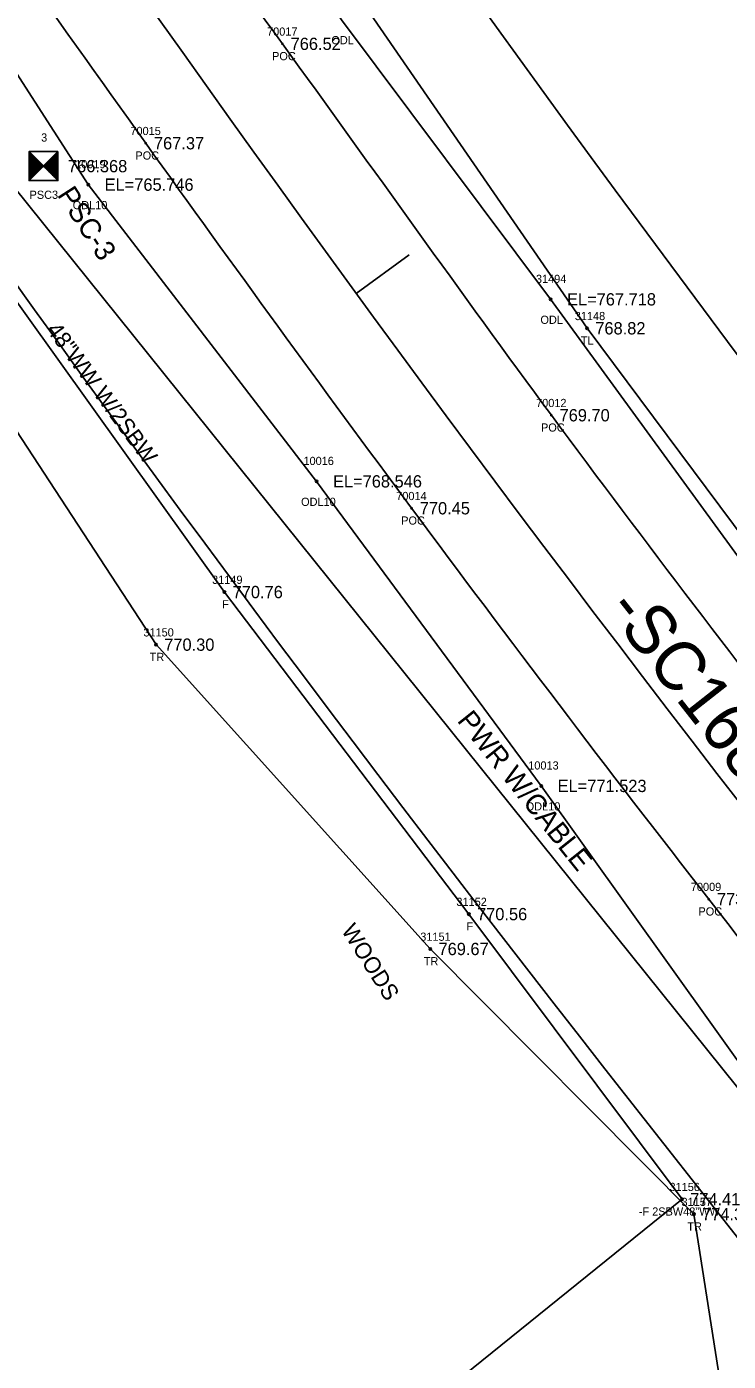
# Model space of a CAD drawing. Extents: x 1375131 to 1378678, y 999028 to 1004053.
# Drawn here: x 1378040.5 to 1378126.3, y 1000372 to 1000535.2 of the extents above; entities that cross this region are included whole.
import ezdxf

# ---------------------------------------------------------------- set-up
doc = ezdxf.new("R2010")
doc.units = 0
for name, color, linetype in [('RD_EX_Fence_Other', 7, 'Continuous'), ('RD_EX_Fence_Other_txCode', 7, 'Continuous'), ('RD_EX_H2O', 7, 'Continuous'), ('RD_EX_H2O_txCode', 7, 'Continuous'), ('RD_EX_Road', 7, 'Continuous'), ('RD_EX_Road_txCode', 7, 'Continuous'), ('RD_EX_RW', 7, 'Continuous'), ('RD_EX_SU_Elec', 7, 'Continuous'), ('RD_EX_TX_Fence_Other_ELEV', 7, 'Continuous'), ('RD_EX_TX_H2O_ELEV', 7, 'Continuous'), ('RD_EX_TX_Road_ELEV', 7, 'Continuous'), ('RD_EX_TX_VEG_ELEV', 7, 'Continuous'), ('RD_EX_VEG', 7, 'Continuous'), ('RD_EX_VEG_txCode', 7, 'Continuous'), ('RD_HC_Cl', 7, 'Continuous'), ('RD_HC_Data', 7, 'Continuous'), ('RD_HC_Data_Tic', 7, 'Continuous'), ('RD_HC_Survey', 7, 'Continuous'), ('RD_HC_Survey_ELEV', 7, 'Continuous'), ('RD_HC_txCode', 7, 'Continuous'), ('RD_SMD_Locator', 7, 'Continuous'), ('RD_TX_Misc1', 7, 'Continuous'), ('RD_TX_Misc2', 7, 'Continuous'), ('RD_TX_Utilities', 7, 'Continuous')]:
    doc.layers.add(name, color=color, linetype=linetype)

msp = doc.modelspace()

# ---------------------------------------------------------------- linework, layer by layer
at = {"layer": 'RD_EX_Fence_Other'}
msp.add_line((1378120.64, 1000391.86), (1378063.92, 1000346.11), dxfattribs=at)
msp.add_lwpolyline([(1377931.18, 1000664.74), (1377962.69, 1000614.46), (1378000.62, 1000557.28), (1378027.91, 1000517.45), (1378064.7, 1000466.08), (1378094.58, 1000426.71), (1378120.64, 1000391.86)], dxfattribs=at)
at = {"layer": 'RD_EX_H2O'}
for points in [[(1378150.92, 1000378.55), (1378129.93, 1000405.36), (1378103.43, 1000442.38), (1378075.97, 1000479.61), (1378048.05, 1000515.88), (1378024, 1000553.21), (1377996.39, 1000591.76), (1377970.53, 1000631.66), (1377963.48, 1000646.08)], [(1378187.96, 1000391.62), (1378166.95, 1000418.07), (1378136.83, 1000457.58), (1378104.58, 1000501.86), (1378079.02, 1000536.04), (1378053.9, 1000573.86), (1378029.31, 1000608.17), (1378022.93, 1000618.73)]]:
    msp.add_lwpolyline(points, dxfattribs=at)
at = {"layer": 'RD_EX_Road'}
for points in [[(1378177.15, 1000392.85), (1378139.73, 1000441.52), (1378104.67, 1000487.69), (1378071.79, 1000533.09), (1378038.45, 1000579.8), (1378007.55, 1000627.96), (1377974.27, 1000678.86), (1377944.47, 1000727.12), (1377913.03, 1000778.58), (1377899.67, 1000800.29)], [(1378161.36, 1000381.16), (1378123.91, 1000428.54), (1378087.58, 1000476.32), (1378055.08, 1000520.94), (1378021.67, 1000568.71), (1377989.95, 1000617.08), (1377957.33, 1000668.38), (1377927.53, 1000716.55), (1377895.41, 1000768.82), (1377883.75, 1000788.5)]]:
    msp.add_spline(points, degree=3, dxfattribs=at)
at = {"layer": 'RD_EX_RW'}
msp.add_line((1378111.22, 1000407.8), (1378147.34, 1000361.8), dxfattribs=at)
for radius in [2667, 2733]:
    msp.add_arc((1380260.77, 1002095.62), radius, 211.36799, 218.13892, dxfattribs=at)
at = {"layer": 'RD_EX_SU_Elec'}
msp.add_lwpolyline([(1377798.03, 1000893.79), (1378025.9, 1000531.77), (1378278.5, 1000217.55)], dxfattribs=at)
at = {"layer": 'RD_EX_VEG'}
for points in [[(1377698.52, 1000917.3), (1377753.14, 1000944.68), (1377782.86, 1000890.37), (1377819.02, 1000831), (1377844.41, 1000789.91), (1377879.22, 1000734.35), (1377912.22, 1000680.73), (1377954.28, 1000611.32), (1377992.95, 1000554.02), (1378022.09, 1000512.01), (1378056.34, 1000459.65), (1378089.87, 1000422.45), (1378122.09, 1000390.03), (1378125.27, 1000369.76), (1378093.99, 1000348.6)], [(1377975.86, 1000867.47), (1377940.96, 1000846.12), (1377905.66, 1000824.77), (1377936.14, 1000772.34), (1377973.26, 1000709.66), (1378011.8, 1000643.94), (1378051.79, 1000581.32), (1378077.27, 1000544.45), (1378109.04, 1000498.32), (1378149.58, 1000443.93), (1378185.36, 1000398.58)]]:
    msp.add_lwpolyline(points, dxfattribs=at)
at = {"layer": 'RD_HC_Cl'}
msp.add_arc((1380260.77, 1002095.62), 2700, 211.36799, 218.13892, dxfattribs=at)
at = {"layer": 'RD_HC_Data_Tic'}
msp.add_line((1378080.81, 1000502.58), (1378087.27, 1000507.3), dxfattribs=at)
at = {"layer": 'RD_HC_Survey'}
for p, q in [((1378040.81, 1000519.91), (1378044.34, 1000516.37)), ((1378044.34, 1000519.91), (1378040.81, 1000516.37)), ((1378040.83, 1000519.88), (1378040.83, 1000516.4)), ((1378040.86, 1000519.86), (1378040.86, 1000516.42)), ((1378040.88, 1000519.83), (1378040.88, 1000516.45)), ((1378040.91, 1000519.81), (1378040.91, 1000516.47)), ((1378040.93, 1000519.78), (1378040.93, 1000516.5)), ((1378040.96, 1000519.76), (1378040.96, 1000516.52)), ((1378040.98, 1000519.73), (1378040.98, 1000516.55)), ((1378041.01, 1000519.71), (1378041.01, 1000516.57)), ((1378041.03, 1000519.68), (1378041.03, 1000516.6)), ((1378041.06, 1000519.66), (1378041.06, 1000516.62)), ((1378041.08, 1000519.63), (1378041.08, 1000516.65)), ((1378041.11, 1000519.61), (1378041.11, 1000516.67)), ((1378041.13, 1000519.58), (1378041.13, 1000516.7)), ((1378041.16, 1000519.56), (1378041.16, 1000516.72)), ((1378041.18, 1000519.53), (1378041.18, 1000516.75)), ((1378041.21, 1000519.51), (1378041.21, 1000516.77)), ((1378041.23, 1000519.48), (1378041.23, 1000516.8)), ((1378041.26, 1000519.46), (1378041.26, 1000516.82)), ((1378041.28, 1000519.43), (1378041.28, 1000516.85)), ((1378041.31, 1000519.41), (1378041.31, 1000516.87)), ((1378041.33, 1000519.38), (1378041.33, 1000516.9)), ((1378041.36, 1000519.36), (1378041.36, 1000516.92)), ((1378041.38, 1000519.33), (1378041.38, 1000516.95)), ((1378041.41, 1000519.31), (1378041.41, 1000516.97)), ((1378041.43, 1000519.28), (1378041.43, 1000517)), ((1378041.46, 1000519.26), (1378041.46, 1000517.02)), ((1378041.48, 1000519.23), (1378041.48, 1000517.05)), ((1378041.51, 1000519.21), (1378041.51, 1000517.07)), ((1378043.64, 1000519.21), (1378043.64, 1000517.07)), ((1378043.67, 1000519.23), (1378043.67, 1000517.05)), ((1378043.69, 1000519.26), (1378043.69, 1000517.02)), ((1378043.72, 1000519.28), (1378043.72, 1000517)), ((1378043.74, 1000519.31), (1378043.74, 1000516.97)), ((1378043.77, 1000519.33), (1378043.77, 1000516.95)), ((1378043.79, 1000519.36), (1378043.79, 1000516.92)), ((1378043.82, 1000519.38), (1378043.82, 1000516.9)), ((1378043.84, 1000519.41), (1378043.84, 1000516.87)), ((1378043.87, 1000519.43), (1378043.87, 1000516.85)), ((1378043.89, 1000519.46), (1378043.89, 1000516.82)), ((1378043.92, 1000519.48), (1378043.92, 1000516.8)), ((1378043.94, 1000519.51), (1378043.94, 1000516.77)), ((1378043.97, 1000519.53), (1378043.97, 1000516.75)), ((1378043.99, 1000519.56), (1378043.99, 1000516.72)), ((1378044.02, 1000519.58), (1378044.02, 1000516.7)), ((1378044.04, 1000519.61), (1378044.04, 1000516.67)), ((1378044.07, 1000519.63), (1378044.07, 1000516.65)), ((1378044.09, 1000519.66), (1378044.09, 1000516.62)), ((1378044.12, 1000519.68), (1378044.12, 1000516.6)), ((1378044.14, 1000519.71), (1378044.14, 1000516.57)), ((1378044.17, 1000519.73), (1378044.17, 1000516.55)), ((1378044.19, 1000519.76), (1378044.19, 1000516.52)), ((1378044.22, 1000519.78), (1378044.22, 1000516.5)), ((1378044.24, 1000519.81), (1378044.24, 1000516.47)), ((1378044.27, 1000519.83), (1378044.27, 1000516.45)), ((1378044.29, 1000519.86), (1378044.29, 1000516.42)), ((1378044.32, 1000519.88), (1378044.32, 1000516.4)), ((1378041.53, 1000519.18), (1378041.53, 1000517.1)), ((1378041.56, 1000519.16), (1378041.56, 1000517.12)), ((1378041.58, 1000519.13), (1378041.58, 1000517.15)), ((1378041.61, 1000519.11), (1378041.61, 1000517.17)), ((1378041.63, 1000519.08), (1378041.63, 1000517.2)), ((1378041.66, 1000519.06), (1378041.66, 1000517.22)), ((1378041.68, 1000519.03), (1378041.68, 1000517.25)), ((1378041.71, 1000519.01), (1378041.71, 1000517.27)), ((1378041.73, 1000518.98), (1378041.73, 1000517.3)), ((1378041.76, 1000518.96), (1378041.76, 1000517.32)), ((1378041.78, 1000518.93), (1378041.78, 1000517.35)), ((1378041.81, 1000518.91), (1378041.81, 1000517.37)), ((1378041.83, 1000518.88), (1378041.83, 1000517.4)), ((1378041.86, 1000518.86), (1378041.86, 1000517.42)), ((1378041.88, 1000518.83), (1378041.88, 1000517.45)), ((1378041.91, 1000518.81), (1378041.91, 1000517.47)), ((1378041.93, 1000518.78), (1378041.93, 1000517.5)), ((1378041.96, 1000518.76), (1378041.96, 1000517.52)), ((1378041.98, 1000518.73), (1378041.98, 1000517.55)), ((1378042.01, 1000518.71), (1378042.01, 1000517.57)), ((1378042.03, 1000518.68), (1378042.03, 1000517.6)), ((1378042.06, 1000518.66), (1378042.06, 1000517.62)), ((1378042.08, 1000518.63), (1378042.08, 1000517.65)), ((1378042.11, 1000518.61), (1378042.11, 1000517.67)), ((1378042.13, 1000518.58), (1378042.13, 1000517.7)), ((1378042.16, 1000518.56), (1378042.16, 1000517.72)), ((1378042.18, 1000518.53), (1378042.18, 1000517.75)), ((1378042.21, 1000518.51), (1378042.21, 1000517.77)), ((1378042.23, 1000518.48), (1378042.23, 1000517.8)), ((1378042.26, 1000518.46), (1378042.26, 1000517.82)), ((1378042.28, 1000518.43), (1378042.28, 1000517.85)), ((1378042.31, 1000518.41), (1378042.31, 1000517.87)), ((1378042.33, 1000518.38), (1378042.33, 1000517.9)), ((1378042.36, 1000518.36), (1378042.36, 1000517.92)), ((1378042.38, 1000518.33), (1378042.38, 1000517.95)), ((1378042.41, 1000518.31), (1378042.41, 1000517.97)), ((1378042.43, 1000518.28), (1378042.43, 1000518)), ((1378042.46, 1000518.26), (1378042.46, 1000518.02)), ((1378042.48, 1000518.23), (1378042.48, 1000518.05)), ((1378042.51, 1000518.21), (1378042.51, 1000518.07)), ((1378042.53, 1000518.18), (1378042.53, 1000518.1)), ((1378042.56, 1000518.16), (1378042.56, 1000518.12)), ((1378042.59, 1000518.16), (1378042.59, 1000518.12)), ((1378042.62, 1000518.18), (1378042.62, 1000518.1)), ((1378042.64, 1000518.21), (1378042.64, 1000518.07)), ((1378042.67, 1000518.23), (1378042.67, 1000518.05)), ((1378042.69, 1000518.26), (1378042.69, 1000518.02)), ((1378042.72, 1000518.28), (1378042.72, 1000518)), ((1378042.74, 1000518.31), (1378042.74, 1000517.97)), ((1378042.77, 1000518.33), (1378042.77, 1000517.95)), ((1378042.79, 1000518.36), (1378042.79, 1000517.92)), ((1378042.82, 1000518.38), (1378042.82, 1000517.9)), ((1378042.84, 1000518.41), (1378042.84, 1000517.87)), ((1378042.87, 1000518.43), (1378042.87, 1000517.85)), ((1378042.89, 1000518.46), (1378042.89, 1000517.82)), ((1378042.92, 1000518.48), (1378042.92, 1000517.8)), ((1378042.94, 1000518.51), (1378042.94, 1000517.77)), ((1378042.97, 1000518.53), (1378042.97, 1000517.75)), ((1378042.99, 1000518.56), (1378042.99, 1000517.72)), ((1378043.02, 1000518.58), (1378043.02, 1000517.7)), ((1378043.04, 1000518.61), (1378043.04, 1000517.67)), ((1378043.07, 1000518.63), (1378043.07, 1000517.65)), ((1378043.09, 1000518.66), (1378043.09, 1000517.62)), ((1378043.12, 1000518.68), (1378043.12, 1000517.6)), ((1378043.14, 1000518.71), (1378043.14, 1000517.57)), ((1378043.17, 1000518.73), (1378043.17, 1000517.55)), ((1378043.19, 1000518.76), (1378043.19, 1000517.52)), ((1378043.22, 1000518.78), (1378043.22, 1000517.5)), ((1378043.24, 1000518.81), (1378043.24, 1000517.47)), ((1378043.27, 1000518.83), (1378043.27, 1000517.45)), ((1378043.29, 1000518.86), (1378043.29, 1000517.42)), ((1378043.32, 1000518.88), (1378043.32, 1000517.4)), ((1378043.34, 1000518.91), (1378043.34, 1000517.37)), ((1378043.37, 1000518.93), (1378043.37, 1000517.35)), ((1378043.39, 1000518.96), (1378043.39, 1000517.32)), ((1378043.42, 1000518.98), (1378043.42, 1000517.3)), ((1378043.44, 1000519.01), (1378043.44, 1000517.27)), ((1378043.47, 1000519.03), (1378043.47, 1000517.25)), ((1378043.49, 1000519.06), (1378043.49, 1000517.22)), ((1378043.52, 1000519.08), (1378043.52, 1000517.2)), ((1378043.54, 1000519.11), (1378043.54, 1000517.17)), ((1378043.57, 1000519.13), (1378043.57, 1000517.15)), ((1378043.59, 1000519.16), (1378043.59, 1000517.12)), ((1378043.62, 1000519.18), (1378043.62, 1000517.1))]:
    msp.add_line(p, q, dxfattribs=at)
msp.add_lwpolyline([(1378044.34, 1000519.91), (1378040.81, 1000519.91), (1378040.81, 1000516.37), (1378044.34, 1000516.37)], close=True, dxfattribs=at)
at = {"layer": 'RD_SMD_Locator'}
for centre, radius in [((1378071.79, 1000533.09), 0.075), ((1378055.08, 1000520.94), 0.075), ((1378042.57, 1000518.14), 0.075), ((1378048.05, 1000515.88), 0.15), ((1378104.58, 1000501.86), 0.15), ((1378109.04, 1000498.32), 0.15), ((1378104.67, 1000487.69), 0.075), ((1378075.97, 1000479.61), 0.15), ((1378087.58, 1000476.32), 0.075), ((1378064.7, 1000466.08), 0.15), ((1378056.34, 1000459.65), 0.15), ((1378103.43, 1000442.38), 0.15), ((1378123.91, 1000428.54), 0.075), ((1378094.58, 1000426.71), 0.15), ((1378089.87, 1000422.45), 0.15), ((1378120.64, 1000391.86), 0.15), ((1378122.09, 1000390.03), 0.15)]:
    msp.add_circle(centre, radius, dxfattribs=at)

# ---------------------------------------------------------------- texts
at = {"layer": 'RD_EX_Fence_Other_txCode'}
for s, p in [('31149', (1378063.19, 1000467.08)), ('F', (1378064.42, 1000464.08)), ('31152', (1378093.06, 1000427.71)), ('F', (1378094.29, 1000424.71)), ('31156', (1378119.11, 1000392.86)), ('-F 2SBW48"WW', (1378115.36, 1000389.86))]:
    msp.add_text(s, height=1, dxfattribs=at).set_placement(p)
at = {"layer": 'RD_EX_H2O_txCode'}
for s, p in [('ODL', (1378077.77, 1000533.04)), ('10019', (1378046.45, 1000517.88)), ('ODL10', (1378046.15, 1000512.88)), ('31494', (1378102.78, 1000503.86)), ('ODL', (1378103.33, 1000498.86)), ('10016', (1378074.36, 1000481.61)), ('ODL10', (1378074.07, 1000476.61)), ('10013', (1378101.84, 1000444.38)), ('ODL10', (1378101.53, 1000439.38))]:
    msp.add_text(s, height=1, dxfattribs=at).set_placement(p)
at = {"layer": 'RD_EX_Road_txCode'}
for s, p in [('70017', (1378069.91, 1000534.09)), ('POC', (1378070.52, 1000531.09)), ('70015', (1378053.2, 1000521.94)), ('POC', (1378053.81, 1000518.94)), ('70012', (1378102.8, 1000488.69)), ('POC', (1378103.4, 1000485.69)), ('70014', (1378085.7, 1000477.32)), ('POC', (1378086.31, 1000474.32)), ('70009', (1378121.72, 1000429.54)), ('POC', (1378122.65, 1000426.54))]:
    msp.add_text(s, height=1, dxfattribs=at).set_placement(p)
at = {"layer": 'RD_EX_TX_Fence_Other_ELEV'}
for s, p in [('770.76', (1378065.7, 1000465.33)), ('770.56', (1378095.58, 1000425.96)), ('774.41', (1378121.64, 1000391.11))]:
    msp.add_text(s, height=1.5, dxfattribs=at).set_placement(p)
at = {"layer": 'RD_EX_TX_H2O_ELEV'}
for s, p in [('EL=765.746', (1378050.05, 1000515.13)), ('EL=767.718', (1378106.58, 1000501.11)), ('EL=768.546', (1378077.97, 1000478.86)), ('EL=771.523', (1378105.43, 1000441.63))]:
    msp.add_text(s, height=1.5, dxfattribs=at).set_placement(p)
at = {"layer": 'RD_EX_TX_Road_ELEV'}
for s, p in [('766.52', (1378072.79, 1000532.34)), ('767.37', (1378056.08, 1000520.19)), ('769.70', (1378105.67, 1000486.94)), ('770.45', (1378088.58, 1000475.57)), ('773.84', (1378124.91, 1000427.79))]:
    msp.add_text(s, height=1.5, dxfattribs=at).set_placement(p)
at = {"layer": 'RD_EX_TX_VEG_ELEV'}
for s, p in [('768.82', (1378110.04, 1000497.57)), ('770.30', (1378057.34, 1000458.9)), ('769.67', (1378090.87, 1000421.7)), ('774.35', (1378123.09, 1000389.28))]:
    msp.add_text(s, height=1.5, dxfattribs=at).set_placement(p)
at = {"layer": 'RD_EX_VEG_txCode'}
for s, p in [('31148', (1378107.53, 1000499.32)), ('TL', (1378108.27, 1000496.32)), ('31150', (1378054.79, 1000460.65)), ('TR', (1378055.55, 1000457.65)), ('31151', (1378088.64, 1000423.45)), ('TR', (1378089.07, 1000420.45)), ('31157', (1378120.58, 1000391.03)), ('TR', (1378121.29, 1000388.03))]:
    msp.add_text(s, height=1, dxfattribs=at).set_placement(p)
at = {"layer": 'RD_HC_Data'}
msp.add_text('-SC168-', height=6, rotation=308.1389, dxfattribs=at).set_placement((1378111.23, 1000463.9))
at = {"layer": 'RD_HC_Survey_ELEV'}
msp.add_text('766.368', height=1.5, dxfattribs=at).set_placement((1378045.57, 1000517.39))
at = {"layer": 'RD_HC_txCode'}
for s, p in [('3', (1378042.29, 1000521.14)), ('PSC3', (1378040.87, 1000514.14))]:
    msp.add_text(s, height=1, dxfattribs=at).set_placement(p)
at = {"layer": 'RD_TX_Misc1'}
msp.add_text('PSC-3', height=2.5, rotation=302.8608, dxfattribs=at).set_placement((1378044.18, 1000514.63))
at = {"layer": 'RD_TX_Misc2'}
for s, rotation, p in [('48"WW W/2SBW', 306.317, (1378042.85, 1000498.12)), ('48"WW W/2SBW', 306.317, (1378042.85, 1000498.12)), ('WOODS', 302.3586, (1378078.93, 1000424.72))]:
    msp.add_text(s, height=2, rotation=rotation, dxfattribs=at).set_placement(p)
at = {"layer": 'RD_TX_Utilities'}
msp.add_text('PWR W/CABLE', height=2.5, rotation=308.6686, dxfattribs=at).set_placement((1378093.06, 1000450.33))

doc.saveas('drawing.dxf')
